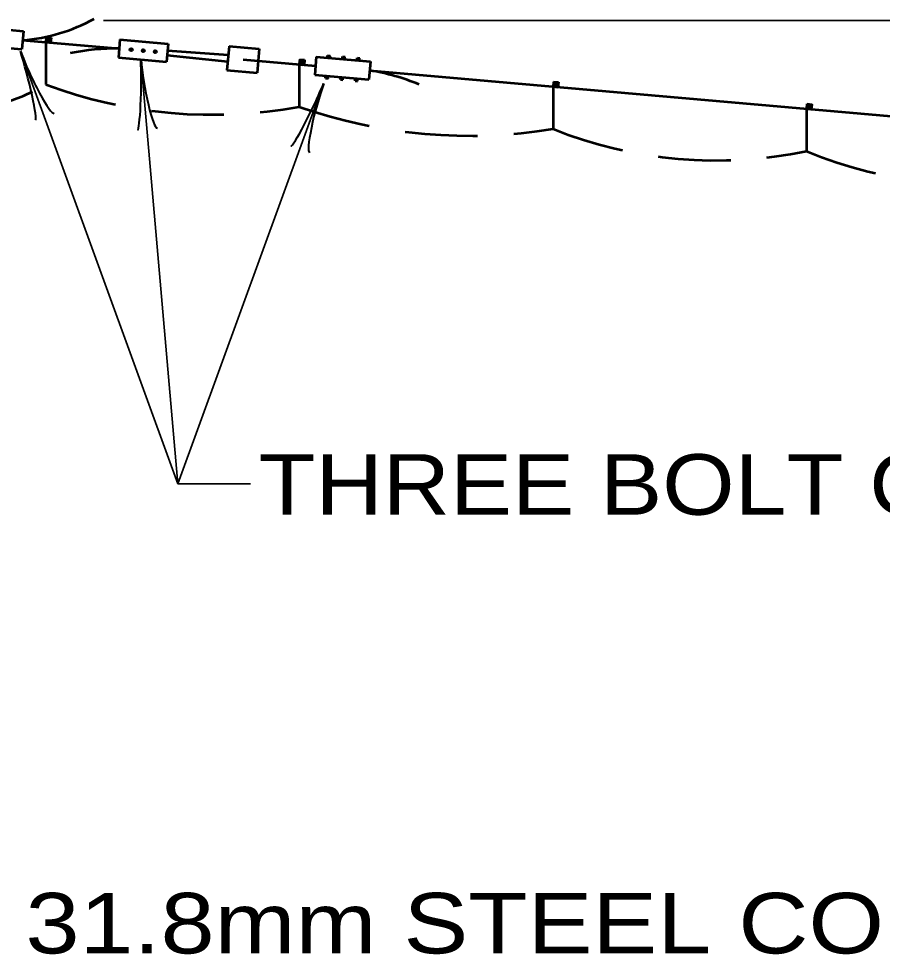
# Model space of a CAD drawing. Extents: x 14808 to 15663, y 10944 to 11488.
# Drawn here: x 14967.64 to 15010.43, y 11360.28 to 11406.65 of the extents above; entities that cross this region are included whole.
import ezdxf
from ezdxf.enums import TextEntityAlignment as Align

# ---------------------------------------------------------------- set-up
doc = ezdxf.new("R2010")
doc.units = 0
doc.header["$LTSCALE"] = 1.2
doc.linetypes.add('MEDIUM_DASHED', pattern=[4.5, 3, -1.5])
doc.layers.add('1', color=7, linetype='Continuous', lineweight=53)

msp = doc.modelspace()

# ---------------------------------------------------------------- linework, layer by layer
at = {"layer": '1', "lineweight": 35}
for p, q in [((14971.841, 11406.572), (15072.654, 11406.572)), ((14975.531, 11383.605), (14982.748, 11403.433)), ((14975.531, 11383.605), (14979.131, 11383.605))]:
    msp.add_line(p, q, dxfattribs=at)
at = {"layer": '1'}
for p, q in [((14966.082, 11406.195), (14967.875, 11406.038)), ((14967.875, 11406.038), (14967.797, 11405.141)), ((14967.836, 11405.59), (14972.618, 11405.172)), ((14969.005, 11405.731), (14968.984, 11405.492)), ((14969, 11405.671), (14968.984, 11405.492)), ((14968.984, 11405.492), (14969.163, 11405.476)), ((14968.984, 11405.492), (14968.984, 11403.392)), ((14968.984, 11405.492), (14969.223, 11405.471)), ((14969.021, 11405.73), (14969, 11405.491)), ((14969, 11405.671), (14969.179, 11405.656)), ((14969.016, 11405.67), (14969, 11405.491)), ((14969.005, 11405.731), (14969.244, 11405.71)), ((14969.039, 11405.728), (14969.019, 11405.489)), ((14969.034, 11405.668), (14969.019, 11405.489)), ((14969.058, 11405.727), (14969.037, 11405.488)), ((14969.052, 11405.667), (14969.037, 11405.488)), ((14969.076, 11405.725), (14969.055, 11405.486)), ((14969.07, 11405.665), (14969.055, 11405.486)), ((14969.085, 11405.724), (14969.064, 11405.485)), ((14969.098, 11405.723), (14969.077, 11405.484)), ((14969.093, 11405.663), (14969.077, 11405.484)), ((14969.111, 11405.722), (14969.091, 11405.483)), ((14969.106, 11405.662), (14969.091, 11405.483)), ((14969.124, 11405.721), (14969.103, 11405.482)), ((14969.134, 11405.72), (14969.113, 11405.481)), ((14969.129, 11405.66), (14969.113, 11405.481)), ((14969.153, 11405.718), (14969.132, 11405.479)), ((14969.147, 11405.659), (14969.132, 11405.479)), ((14969.17, 11405.717), (14969.149, 11405.478)), ((14969.165, 11405.657), (14969.149, 11405.478)), ((14969.185, 11405.716), (14969.163, 11405.477)), ((14969.179, 11405.656), (14969.163, 11405.476)), ((14969.197, 11405.714), (14969.176, 11405.475)), ((14969.209, 11405.713), (14969.188, 11405.474)), ((14969.221, 11405.712), (14969.2, 11405.473)), ((14969.233, 11405.711), (14969.212, 11405.472)), ((14969.244, 11405.71), (14969.223, 11405.471)), ((14972.657, 11405.62), (14972.578, 11404.723)), ((14972.657, 11405.62), (14975.048, 11405.411)), ((14975.048, 11405.411), (14974.969, 11404.514)), ((14966.004, 11405.298), (14967.797, 11405.141)), ((14975.019, 11405.078), (14978.024, 11404.868)), ((14978.062, 11405.296), (14977.957, 11404.1)), ((14978.062, 11405.296), (14979.556, 11405.165)), ((14979.556, 11405.165), (14979.451, 11403.97)), ((14972.578, 11404.723), (14974.969, 11404.514)), ((14974.998, 11404.843), (14977.995, 11404.528)), ((14978.757, 11404.633), (14982.343, 11404.319)), ((14981.562, 11404.629), (14981.541, 11404.39)), ((14981.557, 11404.569), (14981.541, 11404.39)), ((14981.578, 11404.628), (14981.557, 11404.389)), ((14981.557, 11404.569), (14981.736, 11404.554)), ((14981.573, 11404.568), (14981.557, 11404.389)), ((14981.562, 11404.629), (14981.801, 11404.608)), ((14981.596, 11404.626), (14981.575, 11404.387)), ((14981.591, 11404.566), (14981.575, 11404.387)), ((14981.614, 11404.625), (14981.593, 11404.385)), ((14981.609, 11404.565), (14981.593, 11404.385)), ((14981.633, 11404.623), (14981.612, 11404.384)), ((14981.627, 11404.563), (14981.612, 11404.384)), ((14981.642, 11404.622), (14981.621, 11404.383)), ((14981.655, 11404.621), (14981.634, 11404.382)), ((14981.649, 11404.561), (14981.634, 11404.382)), ((14981.668, 11404.62), (14981.647, 11404.381)), ((14981.663, 11404.56), (14981.647, 11404.381)), ((14981.681, 11404.619), (14981.66, 11404.38)), ((14981.691, 11404.618), (14981.67, 11404.379)), ((14981.686, 11404.558), (14981.67, 11404.379)), ((14981.709, 11404.616), (14981.688, 11404.377)), ((14981.704, 11404.556), (14981.688, 11404.377)), ((14981.727, 11404.615), (14981.706, 11404.376)), ((14981.722, 11404.555), (14981.706, 11404.376)), ((14981.741, 11404.613), (14981.72, 11404.374)), ((14981.736, 11404.554), (14981.72, 11404.374)), ((14981.754, 11404.612), (14981.733, 11404.373)), ((14981.766, 11404.611), (14981.745, 11404.372)), ((14981.778, 11404.61), (14981.757, 11404.371)), ((14981.79, 11404.609), (14981.769, 11404.37)), ((14981.801, 11404.608), (14981.78, 11404.369)), ((14982.382, 11404.767), (14982.304, 11403.871)), ((14982.382, 11404.767), (14985.072, 11404.532)), ((14982.935, 11404.719), (14982.945, 11404.831)), ((14982.939, 11404.719), (14982.949, 11404.83)), ((14982.945, 11404.831), (14983.064, 11404.82)), ((14982.945, 11404.718), (14982.955, 11404.83)), ((14982.954, 11404.717), (14982.964, 11404.829)), ((14982.961, 11404.717), (14982.971, 11404.829)), ((14982.966, 11404.716), (14982.975, 11404.828)), ((14982.975, 11404.715), (14982.985, 11404.827)), ((14982.982, 11404.715), (14982.992, 11404.827)), ((14982.986, 11404.714), (14982.996, 11404.826)), ((14982.986, 11404.714), (14982.996, 11404.826)), ((14982.993, 11404.714), (14983.003, 11404.826)), ((14983, 11404.713), (14983.01, 11404.825)), ((14983.008, 11404.713), (14983.018, 11404.824)), ((14983.011, 11404.712), (14983.021, 11404.824)), ((14983.019, 11404.712), (14983.029, 11404.823)), ((14983.027, 11404.711), (14983.037, 11404.823)), ((14983.029, 11404.711), (14983.039, 11404.823)), ((14983.031, 11404.711), (14983.041, 11404.822)), ((14983.04, 11404.71), (14983.05, 11404.822)), ((14983.042, 11404.71), (14983.052, 11404.821)), ((14983.045, 11404.709), (14983.055, 11404.821)), ((14983.054, 11404.708), (14983.064, 11404.82)), ((14983.667, 11404.655), (14983.678, 11404.777)), ((14983.674, 11404.654), (14983.685, 11404.776)), ((14983.678, 11404.777), (14983.797, 11404.767)), ((14983.679, 11404.654), (14983.689, 11404.776)), ((14983.681, 11404.654), (14983.692, 11404.776)), ((14983.685, 11404.653), (14983.696, 11404.775)), ((14983.69, 11404.653), (14983.7, 11404.775)), ((14983.697, 11404.652), (14983.707, 11404.774)), ((14983.699, 11404.652), (14983.71, 11404.774)), ((14983.703, 11404.652), (14983.714, 11404.774)), ((14983.703, 11404.652), (14983.714, 11404.774)), ((14983.705, 11404.651), (14983.716, 11404.774)), ((14983.708, 11404.651), (14983.718, 11404.773)), ((14983.712, 11404.651), (14983.723, 11404.773)), ((14983.712, 11404.651), (14983.723, 11404.773)), ((14983.714, 11404.651), (14983.725, 11404.773)), ((14983.714, 11404.651), (14983.725, 11404.773)), ((14983.721, 11404.65), (14983.732, 11404.772)), ((14983.725, 11404.65), (14983.736, 11404.772)), ((14983.727, 11404.65), (14983.738, 11404.772)), ((14983.732, 11404.649), (14983.743, 11404.771)), ((14983.736, 11404.649), (14983.747, 11404.771)), ((14983.736, 11404.649), (14983.747, 11404.771)), ((14983.737, 11404.649), (14983.747, 11404.771)), ((14983.746, 11404.648), (14983.756, 11404.77)), ((14983.755, 11404.647), (14983.765, 11404.769)), ((14983.757, 11404.647), (14983.768, 11404.769)), ((14983.761, 11404.647), (14983.772, 11404.769)), ((14983.77, 11404.646), (14983.781, 11404.768)), ((14983.775, 11404.645), (14983.785, 11404.768)), ((14983.779, 11404.645), (14983.79, 11404.767)), ((14983.787, 11404.644), (14983.797, 11404.767)), ((14984.399, 11404.591), (14984.41, 11404.713)), ((14984.405, 11404.59), (14984.415, 11404.713)), ((14984.409, 11404.59), (14984.42, 11404.712)), ((14984.41, 11404.713), (14984.53, 11404.703)), ((14984.418, 11404.589), (14984.429, 11404.712)), ((14984.418, 11404.589), (14984.429, 11404.712)), ((14984.423, 11404.589), (14984.433, 11404.711)), ((14984.429, 11404.588), (14984.44, 11404.711)), ((14984.436, 11404.588), (14984.447, 11404.71)), ((14984.436, 11404.588), (14984.447, 11404.71)), ((14984.445, 11404.587), (14984.456, 11404.709)), ((14984.454, 11404.586), (14984.465, 11404.709)), ((14984.46, 11404.585), (14984.471, 11404.708)), ((14984.463, 11404.585), (14984.473, 11404.708)), ((14984.474, 11404.584), (14984.485, 11404.707)), ((14984.483, 11404.583), (14984.493, 11404.706)), ((14984.483, 11404.583), (14984.494, 11404.706)), ((14984.49, 11404.583), (14984.5, 11404.705)), ((14984.49, 11404.583), (14984.5, 11404.705)), ((14984.492, 11404.583), (14984.503, 11404.705)), ((14984.503, 11404.582), (14984.514, 11404.704)), ((14984.503, 11404.582), (14984.514, 11404.704)), ((14984.505, 11404.582), (14984.516, 11404.704)), ((14984.516, 11404.581), (14984.527, 11404.703)), ((14984.518, 11404.58), (14984.529, 11404.703)), ((14984.519, 11404.58), (14984.53, 11404.703)), ((14985.072, 11404.532), (14984.993, 11403.635)), ((14977.957, 11404.1), (14979.451, 11403.97)), ((14981.541, 11404.39), (14981.72, 11404.374)), ((14981.541, 11404.39), (14981.541, 11402.29)), ((14981.541, 11404.39), (14981.78, 11404.369)), ((14985.033, 11404.084), (15028.363, 11400.293)), ((14982.304, 11403.871), (14983.649, 11403.753)), ((14982.846, 11403.703), (14982.857, 11403.822)), ((14982.846, 11403.703), (14982.966, 11403.692)), ((14982.85, 11403.702), (14982.86, 11403.822)), ((14982.86, 11403.702), (14982.87, 11403.821)), ((14982.869, 11403.701), (14982.879, 11403.82)), ((14982.869, 11403.701), (14982.879, 11403.82)), ((14982.88, 11403.7), (14982.89, 11403.819)), ((14982.882, 11403.7), (14982.892, 11403.819)), ((14982.891, 11403.699), (14982.901, 11403.818)), ((14982.891, 11403.699), (14982.901, 11403.818)), ((14982.901, 11403.698), (14982.911, 11403.818)), ((14982.904, 11403.698), (14982.914, 11403.817)), ((14982.91, 11403.697), (14982.92, 11403.817)), ((14982.917, 11403.697), (14982.928, 11403.816)), ((14982.926, 11403.696), (14982.937, 11403.815)), ((14982.933, 11403.695), (14982.944, 11403.815)), ((14982.945, 11403.694), (14982.955, 11403.814)), ((14982.956, 11403.693), (14982.966, 11403.813)), ((14982.96, 11403.693), (14982.97, 11403.812)), ((14982.966, 11403.692), (14982.976, 11403.812)), ((14983.578, 11403.639), (14983.589, 11403.758)), ((14983.578, 11403.639), (14983.698, 11403.628)), ((14983.586, 11403.638), (14983.597, 11403.757)), ((14983.597, 11403.637), (14983.608, 11403.757)), ((14983.597, 11403.637), (14983.608, 11403.757)), ((14983.603, 11403.636), (14983.614, 11403.756)), ((14983.611, 11403.636), (14983.621, 11403.755)), ((14983.615, 11403.635), (14983.625, 11403.755)), ((14983.624, 11403.635), (14983.634, 11403.754)), ((14983.633, 11403.634), (14983.643, 11403.753)), ((14983.633, 11403.634), (14983.643, 11403.753)), ((14983.637, 11403.633), (14983.648, 11403.753)), ((14983.638, 11403.633), (14983.649, 11403.753)), ((14983.642, 11403.633), (14983.652, 11403.753)), ((14983.646, 11403.633), (14983.656, 11403.752)), ((14983.649, 11403.753), (14984.993, 11403.635)), ((14983.655, 11403.632), (14983.665, 11403.751)), ((14983.658, 11403.632), (14983.668, 11403.751)), ((14983.666, 11403.631), (14983.677, 11403.75)), ((14983.671, 11403.631), (14983.681, 11403.75)), ((14983.682, 11403.63), (14983.693, 11403.749)), ((14983.684, 11403.629), (14983.695, 11403.749)), ((14983.684, 11403.629), (14983.695, 11403.749)), ((14983.693, 11403.629), (14983.704, 11403.748)), ((14983.698, 11403.628), (14983.708, 11403.748)), ((14984.31, 11403.575), (14984.321, 11403.694)), ((14984.31, 11403.575), (14984.43, 11403.564)), ((14984.32, 11403.574), (14984.33, 11403.693)), ((14984.322, 11403.574), (14984.332, 11403.693)), ((14984.326, 11403.573), (14984.337, 11403.693)), ((14984.331, 11403.573), (14984.341, 11403.692)), ((14984.333, 11403.573), (14984.343, 11403.692)), ((14984.335, 11403.572), (14984.346, 11403.692)), ((14984.337, 11403.572), (14984.348, 11403.692)), ((14984.337, 11403.572), (14984.348, 11403.692)), ((14984.342, 11403.572), (14984.352, 11403.691)), ((14984.344, 11403.572), (14984.355, 11403.691)), ((14984.344, 11403.572), (14984.355, 11403.691)), ((14984.353, 11403.571), (14984.364, 11403.69)), ((14984.364, 11403.57), (14984.375, 11403.689)), ((14984.364, 11403.57), (14984.375, 11403.689)), ((14984.369, 11403.57), (14984.379, 11403.689)), ((14984.371, 11403.569), (14984.381, 11403.689)), ((14984.378, 11403.569), (14984.388, 11403.688)), ((14984.389, 11403.568), (14984.399, 11403.687)), ((14984.389, 11403.568), (14984.399, 11403.687)), ((14984.395, 11403.567), (14984.406, 11403.687)), ((14984.398, 11403.567), (14984.408, 11403.686)), ((14984.4, 11403.567), (14984.41, 11403.686)), ((14984.404, 11403.566), (14984.415, 11403.686)), ((14984.411, 11403.566), (14984.422, 11403.685)), ((14984.422, 11403.565), (14984.433, 11403.684)), ((14984.43, 11403.564), (14984.44, 11403.684)), ((14994.138, 11403.529), (14994.117, 11403.289)), ((14994.133, 11403.469), (14994.117, 11403.289)), ((14994.154, 11403.527), (14994.133, 11403.288)), ((14994.133, 11403.469), (14994.312, 11403.453)), ((14994.138, 11403.529), (14994.377, 11403.507)), ((14994.173, 11403.525), (14994.152, 11403.286)), ((14994.191, 11403.524), (14994.17, 11403.285)), ((14994.209, 11403.522), (14994.188, 11403.283)), ((14994.218, 11403.522), (14994.197, 11403.282)), ((14994.231, 11403.52), (14994.21, 11403.281)), ((14994.245, 11403.519), (14994.224, 11403.28)), ((14994.258, 11403.518), (14994.237, 11403.279)), ((14994.267, 11403.517), (14994.247, 11403.278)), ((14994.286, 11403.516), (14994.265, 11403.276)), ((14994.303, 11403.514), (14994.282, 11403.275)), ((14994.318, 11403.513), (14994.297, 11403.274)), ((14994.331, 11403.512), (14994.31, 11403.272)), ((14994.342, 11403.511), (14994.321, 11403.271)), ((14994.354, 11403.51), (14994.333, 11403.27)), ((14994.366, 11403.508), (14994.345, 11403.269)), ((14994.377, 11403.507), (14994.356, 11403.268)), ((14994.117, 11403.289), (14994.297, 11403.274)), ((14994.117, 11403.289), (14994.117, 11401.189)), ((14994.117, 11403.289), (14994.356, 11403.268)), ((14994.149, 11403.467), (14994.133, 11403.288)), ((14994.167, 11403.466), (14994.152, 11403.286)), ((14994.185, 11403.464), (14994.17, 11403.285)), ((14994.204, 11403.462), (14994.188, 11403.283)), ((14994.226, 11403.461), (14994.21, 11403.281)), ((14994.239, 11403.459), (14994.224, 11403.28)), ((14994.262, 11403.457), (14994.247, 11403.278)), ((14994.28, 11403.456), (14994.265, 11403.276)), ((14994.298, 11403.454), (14994.282, 11403.275)), ((14994.312, 11403.453), (14994.297, 11403.274)), ((15006.69, 11402.43), (15006.669, 11402.191)), ((15006.685, 11402.37), (15006.669, 11402.191)), ((15006.669, 11402.191), (15006.849, 11402.175)), ((15006.669, 11402.191), (15006.669, 11400.091)), ((15006.669, 11402.191), (15006.908, 11402.17)), ((15006.685, 11402.37), (15006.864, 11402.355)), ((15006.707, 11402.429), (15006.686, 11402.19)), ((15006.701, 11402.369), (15006.686, 11402.19)), ((15006.69, 11402.43), (15006.929, 11402.409)), ((15006.725, 11402.427), (15006.704, 11402.188)), ((15006.719, 11402.367), (15006.704, 11402.188)), ((15006.743, 11402.426), (15006.722, 11402.186)), ((15006.738, 11402.366), (15006.722, 11402.186)), ((15006.761, 11402.424), (15006.74, 11402.185)), ((15006.756, 11402.364), (15006.74, 11402.185)), ((15006.77, 11402.423), (15006.749, 11402.184)), ((15006.783, 11402.422), (15006.762, 11402.183)), ((15006.778, 11402.362), (15006.762, 11402.183)), ((15006.797, 11402.421), (15006.776, 11402.182)), ((15006.791, 11402.361), (15006.776, 11402.182)), ((15006.81, 11402.42), (15006.789, 11402.181)), ((15006.82, 11402.419), (15006.799, 11402.18)), ((15006.814, 11402.359), (15006.799, 11402.18)), ((15006.838, 11402.417), (15006.817, 11402.178)), ((15006.832, 11402.358), (15006.817, 11402.178)), ((15006.855, 11402.416), (15006.835, 11402.177)), ((15006.85, 11402.356), (15006.835, 11402.177)), ((15006.87, 11402.415), (15006.849, 11402.176)), ((15006.864, 11402.355), (15006.849, 11402.175)), ((15006.883, 11402.413), (15006.862, 11402.174)), ((15006.894, 11402.412), (15006.873, 11402.173)), ((15006.906, 11402.411), (15006.885, 11402.172)), ((15006.918, 11402.41), (15006.897, 11402.171)), ((15006.929, 11402.409), (15006.908, 11402.17))]:
    msp.add_line(p, q, dxfattribs=at)
at = {"layer": '1', "lineweight": 25}
for p, q in [((14967.836, 11405.59), (14968.281, 11405.551)), ((14972.618, 11405.172), (14972.377, 11405.193)), ((14978.757, 11404.633), (14979.503, 11404.567)), ((14982.343, 11404.319), (14981.874, 11404.36)), ((14985.033, 11404.084), (14985.489, 11404.044))]:
    msp.add_line(p, q, dxfattribs=at)
at = {"layer": '1', "lineweight": 35}
msp.add_lwpolyline([(14967.732, 11405.03), (14975.531, 11383.605), (14973.692, 11404.626)], dxfattribs=at)
at = {"layer": '1'}
for centre in [(14973.213, 11405.119), (14973.811, 11405.07), (14974.409, 11405.016)]:
    msp.add_circle(centre, 0.06, dxfattribs=at)
for centre, radius, start, end in [((14967.162, 11414.286), 8.723, 274.4304, 298.9537), ((14972.4, 11394.744), 10.43, 88.8055, 102.2055), ((14983.436, 11393.776), 10.43, 67.1869, 81.1945)]:
    msp.add_arc(centre, radius, start, end, dxfattribs=at)
at = {"layer": '1', "linetype": 'MEDIUM_DASHED'}
for centre, radius, start, end in [((14964.262, 11411.389), 9.287, 240.3596, 300.5594), ((14977.248, 11425.46), 23.564, 249.4706, 280.4975), ((14989.977, 11426.286), 25.436, 250.6292, 279.3671), ((15002.214, 11421.448), 21.817, 248.2157, 281.784), ((15014.662, 11419.161), 20.677, 247.2606, 282.7391)]:
    msp.add_arc(centre, radius, start, end, dxfattribs=at)
at = {"layer": '1', "lineweight": 40}
for centre, major_axis, ratio, start_param, end_param in [((14967.954, 11403.679), (0.523, -2.053), 0.07063, 6.282307, 8.559703), ((14968.492, 11403.912), (-0.909, 1.95), 0.122415, 0.896353, 3.141593), ((14973.556, 11403.264), (-0.026, -2.118), 0.07063, 6.282307, 8.559703), ((14974.136, 11403.35), (-0.373, 2.118), 0.122415, 0.896353, 3.141593), ((14982.05, 11402.257), (-0.919, -1.909), 0.07063, 6.282307, 8.559703), ((14982.612, 11402.089), (0.557, 2.078), 0.122415, 0.896353, 3.141593)]:
    msp.add_ellipse(centre, major_axis=major_axis, ratio=ratio, start_param=start_param, end_param=end_param, dxfattribs=at)

# ---------------------------------------------------------------- texts
at = {"layer": '1', "width": 1.15}
msp.add_text('THREE BOLT CLAMP', height=3, dxfattribs=at).set_placement((14979.528, 11382.066))
at = {"layer": '1', "width": 1.2}
msp.add_text('31.8mm STEEL CONDUIT', height=3, dxfattribs=at).set_placement((15025.221, 11360.32), align=Align.RIGHT)

doc.saveas('drawing.dxf')
